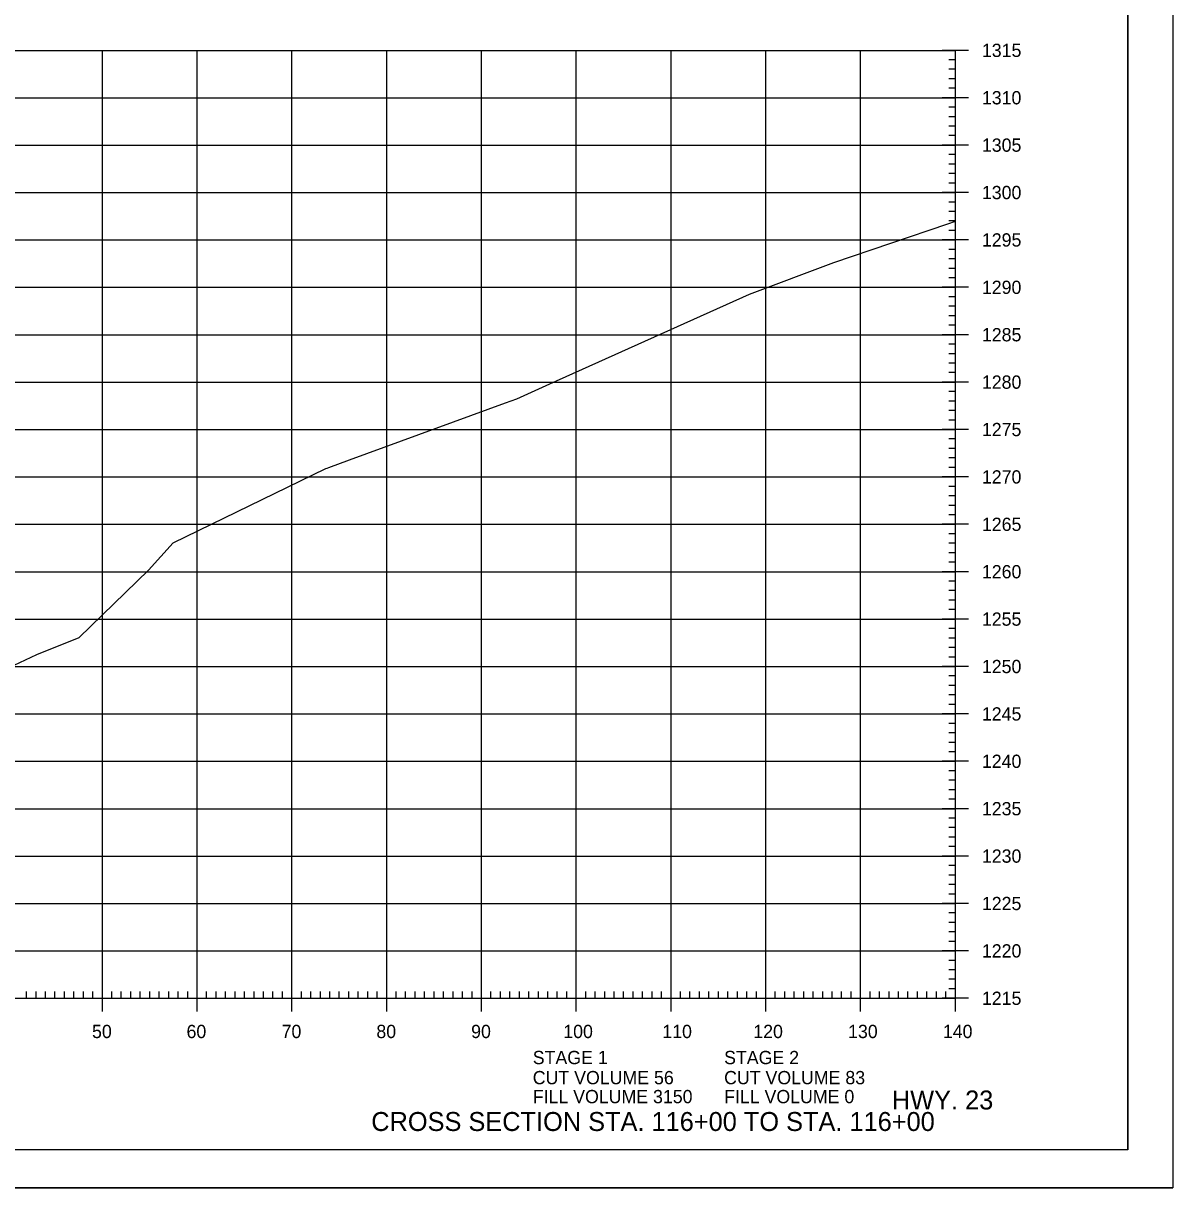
# Model space of a CAD drawing. Extents: x 1406028 to 1412453, y 321733 to 325986.
# Drawn here: x 1406631.5 to 1406752.8, y 324279.4 to 324402.2 of the extents above; entities that cross this region are included whole.
import ezdxf

# ---------------------------------------------------------------- set-up
doc = ezdxf.new("R2010")
doc.units = 0
for name, color, linetype in [('R_Axis', 7, 'Continuous'), ('R_Axis Annot', 7, 'Continuous'), ('R_Border', 7, 'Continuous'), ('R_Draft', 7, 'Continuous'), ('R_Exist Surface', 7, 'Continuous'), ('R_Grid', 7, 'Continuous'), ('R_No Plot', 7, 'Continuous')]:
    doc.layers.add(name, color=color, linetype=linetype)

msp = doc.modelspace()

# ---------------------------------------------------------------- linework, layer by layer
at = {"layer": 'R_Axis'}
for p, q in [((1406731.29, 324399.37), (1406728.49, 324399.37)), ((1406729.89, 324398.37), (1406729.19, 324398.37)), ((1406729.89, 324299.37), (1406729.89, 324399.37)), ((1406729.89, 324397.37), (1406729.19, 324397.37)), ((1406729.89, 324396.37), (1406729.19, 324396.37)), ((1406729.89, 324395.37), (1406729.19, 324395.37)), ((1406731.29, 324394.37), (1406728.49, 324394.37)), ((1406729.89, 324393.37), (1406729.19, 324393.37)), ((1406729.89, 324392.37), (1406729.19, 324392.37)), ((1406729.89, 324391.37), (1406729.19, 324391.37)), ((1406729.89, 324390.37), (1406729.19, 324390.37)), ((1406731.29, 324389.37), (1406728.49, 324389.37)), ((1406729.89, 324388.37), (1406729.19, 324388.37)), ((1406729.89, 324387.37), (1406729.19, 324387.37)), ((1406729.89, 324386.37), (1406729.19, 324386.37)), ((1406729.89, 324385.37), (1406729.19, 324385.37)), ((1406731.29, 324384.37), (1406728.49, 324384.37)), ((1406729.89, 324383.37), (1406729.19, 324383.37)), ((1406729.89, 324382.37), (1406729.19, 324382.37)), ((1406729.89, 324381.37), (1406729.19, 324381.37)), ((1406729.89, 324380.37), (1406729.19, 324380.37)), ((1406731.29, 324379.37), (1406728.49, 324379.37)), ((1406729.89, 324378.37), (1406729.19, 324378.37)), ((1406729.89, 324377.37), (1406729.19, 324377.37)), ((1406729.89, 324376.37), (1406729.19, 324376.37)), ((1406729.89, 324375.37), (1406729.19, 324375.37)), ((1406731.29, 324374.37), (1406728.49, 324374.37)), ((1406729.89, 324373.37), (1406729.19, 324373.37)), ((1406729.89, 324372.37), (1406729.19, 324372.37)), ((1406729.89, 324371.37), (1406729.19, 324371.37)), ((1406729.89, 324370.37), (1406729.19, 324370.37)), ((1406731.29, 324369.37), (1406728.49, 324369.37)), ((1406729.89, 324368.37), (1406729.19, 324368.37)), ((1406729.89, 324367.37), (1406729.19, 324367.37)), ((1406729.89, 324366.37), (1406729.19, 324366.37)), ((1406729.89, 324365.37), (1406729.19, 324365.37)), ((1406731.29, 324364.37), (1406728.49, 324364.37)), ((1406729.89, 324363.37), (1406729.19, 324363.37)), ((1406729.89, 324362.37), (1406729.19, 324362.37)), ((1406729.89, 324361.37), (1406729.19, 324361.37)), ((1406729.89, 324360.37), (1406729.19, 324360.37)), ((1406731.29, 324359.37), (1406728.49, 324359.37)), ((1406729.89, 324358.37), (1406729.19, 324358.37)), ((1406729.89, 324357.37), (1406729.19, 324357.37)), ((1406729.89, 324356.37), (1406729.19, 324356.37)), ((1406729.89, 324355.37), (1406729.19, 324355.37)), ((1406731.29, 324354.37), (1406728.49, 324354.37)), ((1406729.89, 324353.37), (1406729.19, 324353.37)), ((1406729.89, 324352.37), (1406729.19, 324352.37)), ((1406729.89, 324351.37), (1406729.19, 324351.37)), ((1406729.89, 324350.37), (1406729.19, 324350.37)), ((1406731.29, 324349.37), (1406728.49, 324349.37)), ((1406729.89, 324348.37), (1406729.19, 324348.37)), ((1406729.89, 324347.37), (1406729.19, 324347.37)), ((1406729.89, 324346.37), (1406729.19, 324346.37)), ((1406731.29, 324344.37), (1406728.49, 324344.37)), ((1406729.89, 324345.37), (1406729.19, 324345.37)), ((1406729.89, 324343.37), (1406729.19, 324343.37)), ((1406729.89, 324342.37), (1406729.19, 324342.37)), ((1406729.89, 324341.37), (1406729.19, 324341.37)), ((1406731.29, 324339.37), (1406728.49, 324339.37)), ((1406729.89, 324340.37), (1406729.19, 324340.37)), ((1406729.89, 324338.37), (1406729.19, 324338.37)), ((1406729.89, 324337.37), (1406729.19, 324337.37)), ((1406729.89, 324336.37), (1406729.19, 324336.37)), ((1406729.89, 324335.37), (1406729.19, 324335.37)), ((1406731.29, 324334.37), (1406728.49, 324334.37)), ((1406729.89, 324333.37), (1406729.19, 324333.37)), ((1406729.89, 324332.37), (1406729.19, 324332.37)), ((1406729.89, 324331.37), (1406729.19, 324331.37)), ((1406729.89, 324330.37), (1406729.19, 324330.37)), ((1406731.29, 324329.37), (1406728.49, 324329.37)), ((1406729.89, 324328.37), (1406729.19, 324328.37)), ((1406729.89, 324327.37), (1406729.19, 324327.37)), ((1406729.89, 324326.37), (1406729.19, 324326.37)), ((1406729.89, 324325.37), (1406729.19, 324325.37)), ((1406731.29, 324324.37), (1406728.49, 324324.37)), ((1406729.89, 324323.37), (1406729.19, 324323.37)), ((1406729.89, 324322.37), (1406729.19, 324322.37)), ((1406729.89, 324321.37), (1406729.19, 324321.37)), ((1406729.89, 324320.37), (1406729.19, 324320.37)), ((1406731.29, 324319.37), (1406728.49, 324319.37)), ((1406729.89, 324318.37), (1406729.19, 324318.37)), ((1406729.89, 324317.37), (1406729.19, 324317.37)), ((1406729.89, 324316.37), (1406729.19, 324316.37)), ((1406729.89, 324315.37), (1406729.19, 324315.37)), ((1406731.29, 324314.37), (1406728.49, 324314.37)), ((1406729.89, 324313.37), (1406729.19, 324313.37)), ((1406729.89, 324312.37), (1406729.19, 324312.37)), ((1406729.89, 324311.37), (1406729.19, 324311.37)), ((1406729.89, 324310.37), (1406729.19, 324310.37)), ((1406731.29, 324309.37), (1406728.49, 324309.37)), ((1406729.89, 324308.37), (1406729.19, 324308.37)), ((1406729.89, 324307.37), (1406729.19, 324307.37)), ((1406729.89, 324306.37), (1406729.19, 324306.37)), ((1406729.89, 324305.37), (1406729.19, 324305.37)), ((1406731.29, 324304.37), (1406728.49, 324304.37)), ((1406729.89, 324303.37), (1406729.19, 324303.37)), ((1406729.89, 324302.37), (1406729.19, 324302.37)), ((1406729.89, 324301.37), (1406729.19, 324301.37)), ((1406631.89, 324299.37), (1406631.89, 324300.07)), ((1406632.89, 324299.37), (1406632.89, 324300.07)), ((1406633.89, 324299.37), (1406633.89, 324300.07)), ((1406634.89, 324299.37), (1406634.89, 324300.07)), ((1406635.89, 324299.37), (1406635.89, 324300.07)), ((1406636.89, 324299.37), (1406636.89, 324300.07)), ((1406637.89, 324299.37), (1406637.89, 324300.07)), ((1406638.89, 324299.37), (1406638.89, 324300.07)), ((1406639.89, 324297.97), (1406639.89, 324300.77)), ((1406640.89, 324299.37), (1406640.89, 324300.07)), ((1406641.89, 324299.37), (1406641.89, 324300.07)), ((1406642.89, 324299.37), (1406642.89, 324300.07)), ((1406643.89, 324299.37), (1406643.89, 324300.07)), ((1406644.89, 324299.37), (1406644.89, 324300.07)), ((1406645.89, 324299.37), (1406645.89, 324300.07)), ((1406646.89, 324299.37), (1406646.89, 324300.07)), ((1406647.89, 324299.37), (1406647.89, 324300.07)), ((1406648.89, 324299.37), (1406648.89, 324300.07)), ((1406649.89, 324297.97), (1406649.89, 324300.77)), ((1406650.89, 324299.37), (1406650.89, 324300.07)), ((1406651.89, 324299.37), (1406651.89, 324300.07)), ((1406652.89, 324299.37), (1406652.89, 324300.07)), ((1406653.89, 324299.37), (1406653.89, 324300.07)), ((1406654.89, 324299.37), (1406654.89, 324300.07)), ((1406655.89, 324299.37), (1406655.89, 324300.07)), ((1406656.89, 324299.37), (1406656.89, 324300.07)), ((1406657.89, 324299.37), (1406657.89, 324300.07)), ((1406658.89, 324299.37), (1406658.89, 324300.07)), ((1406659.89, 324297.97), (1406659.89, 324300.77)), ((1406660.89, 324299.37), (1406660.89, 324300.07)), ((1406661.89, 324299.37), (1406661.89, 324300.07)), ((1406662.89, 324299.37), (1406662.89, 324300.07)), ((1406663.89, 324299.37), (1406663.89, 324300.07)), ((1406664.89, 324299.37), (1406664.89, 324300.07)), ((1406665.89, 324299.37), (1406665.89, 324300.07)), ((1406666.89, 324299.37), (1406666.89, 324300.07)), ((1406667.89, 324299.37), (1406667.89, 324300.07)), ((1406668.89, 324299.37), (1406668.89, 324300.07)), ((1406669.89, 324297.97), (1406669.89, 324300.77)), ((1406670.89, 324299.37), (1406670.89, 324300.07)), ((1406671.89, 324299.37), (1406671.89, 324300.07)), ((1406672.89, 324299.37), (1406672.89, 324300.07)), ((1406673.89, 324299.37), (1406673.89, 324300.07)), ((1406674.89, 324299.37), (1406674.89, 324300.07)), ((1406675.89, 324299.37), (1406675.89, 324300.07)), ((1406676.89, 324299.37), (1406676.89, 324300.07)), ((1406677.89, 324299.37), (1406677.89, 324300.07)), ((1406678.89, 324299.37), (1406678.89, 324300.07)), ((1406679.89, 324297.97), (1406679.89, 324300.77)), ((1406680.89, 324299.37), (1406680.89, 324300.07)), ((1406681.89, 324299.37), (1406681.89, 324300.07)), ((1406682.89, 324299.37), (1406682.89, 324300.07)), ((1406683.89, 324299.37), (1406683.89, 324300.07)), ((1406684.89, 324299.37), (1406684.89, 324300.07)), ((1406685.89, 324299.37), (1406685.89, 324300.07)), ((1406686.89, 324299.37), (1406686.89, 324300.07)), ((1406687.89, 324299.37), (1406687.89, 324300.07)), ((1406688.89, 324299.37), (1406688.89, 324300.07)), ((1406689.89, 324297.97), (1406689.89, 324300.77)), ((1406690.89, 324299.37), (1406690.89, 324300.07)), ((1406691.89, 324299.37), (1406691.89, 324300.07)), ((1406692.89, 324299.37), (1406692.89, 324300.07)), ((1406693.89, 324299.37), (1406693.89, 324300.07)), ((1406694.89, 324299.37), (1406694.89, 324300.07)), ((1406695.89, 324299.37), (1406695.89, 324300.07)), ((1406696.89, 324299.37), (1406696.89, 324300.07)), ((1406697.89, 324299.37), (1406697.89, 324300.07)), ((1406698.89, 324299.37), (1406698.89, 324300.07)), ((1406699.89, 324297.97), (1406699.89, 324300.77)), ((1406700.89, 324299.37), (1406700.89, 324300.07)), ((1406701.89, 324299.37), (1406701.89, 324300.07)), ((1406702.89, 324299.37), (1406702.89, 324300.07)), ((1406703.89, 324299.37), (1406703.89, 324300.07)), ((1406704.89, 324299.37), (1406704.89, 324300.07)), ((1406705.89, 324299.37), (1406705.89, 324300.07)), ((1406706.89, 324299.37), (1406706.89, 324300.07)), ((1406707.89, 324299.37), (1406707.89, 324300.07)), ((1406708.89, 324299.37), (1406708.89, 324300.07)), ((1406709.89, 324297.97), (1406709.89, 324300.77)), ((1406710.89, 324299.37), (1406710.89, 324300.07)), ((1406711.89, 324299.37), (1406711.89, 324300.07)), ((1406712.89, 324299.37), (1406712.89, 324300.07)), ((1406713.89, 324299.37), (1406713.89, 324300.07)), ((1406714.89, 324299.37), (1406714.89, 324300.07)), ((1406715.89, 324299.37), (1406715.89, 324300.07)), ((1406716.89, 324299.37), (1406716.89, 324300.07)), ((1406717.89, 324299.37), (1406717.89, 324300.07)), ((1406718.89, 324299.37), (1406718.89, 324300.07)), ((1406719.89, 324297.97), (1406719.89, 324300.77)), ((1406720.89, 324299.37), (1406720.89, 324300.07)), ((1406721.89, 324299.37), (1406721.89, 324300.07)), ((1406722.89, 324299.37), (1406722.89, 324300.07)), ((1406723.89, 324299.37), (1406723.89, 324300.07)), ((1406724.89, 324299.37), (1406724.89, 324300.07)), ((1406725.89, 324299.37), (1406725.89, 324300.07)), ((1406726.89, 324299.37), (1406726.89, 324300.07)), ((1406727.89, 324299.37), (1406727.89, 324300.07)), ((1406728.89, 324299.37), (1406728.89, 324300.07)), ((1406729.89, 324300.37), (1406729.19, 324300.37)), ((1406729.89, 324297.97), (1406729.89, 324300.77)), ((1406449.89, 324299.37), (1406729.89, 324299.37)), ((1406731.29, 324299.37), (1406728.49, 324299.37))]:
    msp.add_line(p, q, dxfattribs=at)
at = {"layer": 'R_Border'}
for q in [(1406748.07, 324488.83), (1406431.89, 324283.37)]:
    msp.add_line((1406748.07, 324283.37), q, dxfattribs=at)
at = {"layer": 'R_Exist Surface'}
msp.add_lwpolyline([(1406630.6, 324334.5), (1406632.99, 324335.62), (1406637.44, 324337.42), (1406644.74, 324344.52), (1406647.35, 324347.43), (1406663.46, 324355.24), (1406663.61, 324355.31), (1406663.77, 324355.37), (1406665.95, 324356.16), (1406682.42, 324362.17), (1406683.62, 324362.59), (1406687.11, 324364.2), (1406708.17, 324373.65), (1406717.06, 324376.98), (1406729.09, 324381.06), (1406729.89, 324381.34)], dxfattribs=at)
at = {"layer": 'R_Grid'}
for p, q in [((1406449.89, 324399.37), (1406729.89, 324399.37)), ((1406639.89, 324299.37), (1406639.89, 324399.37)), ((1406649.89, 324299.37), (1406649.89, 324399.37)), ((1406659.89, 324299.37), (1406659.89, 324399.37)), ((1406669.89, 324299.37), (1406669.89, 324399.37)), ((1406679.89, 324299.37), (1406679.89, 324399.37)), ((1406689.89, 324299.37), (1406689.89, 324399.37)), ((1406699.89, 324299.37), (1406699.89, 324399.37)), ((1406709.89, 324299.37), (1406709.89, 324399.37)), ((1406719.89, 324299.37), (1406719.89, 324399.37)), ((1406729.89, 324299.37), (1406729.89, 324399.37)), ((1406449.89, 324394.37), (1406729.89, 324394.37)), ((1406449.89, 324389.37), (1406729.89, 324389.37)), ((1406449.89, 324384.37), (1406729.89, 324384.37)), ((1406449.89, 324379.37), (1406729.89, 324379.37)), ((1406449.89, 324374.37), (1406729.89, 324374.37)), ((1406449.89, 324369.37), (1406729.89, 324369.37)), ((1406449.89, 324364.37), (1406729.89, 324364.37)), ((1406449.89, 324359.37), (1406729.89, 324359.37)), ((1406449.89, 324354.37), (1406729.89, 324354.37)), ((1406449.89, 324349.37), (1406729.89, 324349.37)), ((1406449.89, 324344.37), (1406729.89, 324344.37)), ((1406449.89, 324339.37), (1406729.89, 324339.37)), ((1406449.89, 324334.37), (1406729.89, 324334.37)), ((1406449.89, 324329.37), (1406729.89, 324329.37)), ((1406449.89, 324324.37), (1406729.89, 324324.37)), ((1406449.89, 324319.37), (1406729.89, 324319.37)), ((1406449.89, 324314.37), (1406729.89, 324314.37)), ((1406449.89, 324309.37), (1406729.89, 324309.37)), ((1406449.89, 324304.37), (1406729.89, 324304.37)), ((1406449.89, 324299.37), (1406729.89, 324299.37))]:
    msp.add_line(p, q, dxfattribs=at)
at = {"layer": 'R_No Plot'}
msp.add_line((1406419.49, 324279.39), (1406752.82, 324279.39), dxfattribs=at)
for points in [[(1406419.48, 324492.72), (1406752.82, 324492.72), (1406752.82, 324279.39), (1406419.48, 324279.39)], [(1406665.81, 324488.83), (1406685.43, 324488.83), (1406685.43, 324478.95), (1406701.54, 324478.95), (1406724.74, 324478.95), (1406724.74, 324454.62), (1406748.07, 324454.62), (1406748.07, 324283.37), (1406431.89, 324283.37), (1406431.89, 324488.83)]]:
    msp.add_lwpolyline(points, close=True, dxfattribs=at)

# ---------------------------------------------------------------- texts
at = {"layer": 'R_Axis Annot'}
for s, p in [('1315', (1406732.69, 324398.67)), ('1310', (1406732.69, 324393.67)), ('1305', (1406732.69, 324388.67)), ('1300', (1406732.69, 324383.67)), ('1295', (1406732.69, 324378.67)), ('1290', (1406732.69, 324373.67)), ('1285', (1406732.69, 324368.67)), ('1280', (1406732.69, 324363.67)), ('1275', (1406732.69, 324358.67)), ('1270', (1406732.69, 324353.67)), ('1265', (1406732.69, 324348.67)), ('1260', (1406732.69, 324343.67)), ('1255', (1406732.69, 324338.67)), ('1250', (1406732.69, 324333.67)), ('1245', (1406732.69, 324328.67)), ('1240', (1406732.69, 324323.67)), ('1235', (1406732.69, 324318.67)), ('1230', (1406732.69, 324313.67)), ('1225', (1406732.69, 324308.67)), ('1220', (1406732.69, 324303.67)), ('1215', (1406732.69, 324298.67)), ('50', (1406638.8, 324295.17)), ('60', (1406648.77, 324295.17)), ('70', (1406658.8, 324295.17)), ('80', (1406668.8, 324295.17)), ('90', (1406678.8, 324295.17)), ('100', (1406688.52, 324295.17)), ('110', (1406698.97, 324295.17)), ('120', (1406708.57, 324295.17)), ('130', (1406718.57, 324295.17)), ('140', (1406728.57, 324295.17)), ('STAGE 1', (1406685.3, 324292.42)), ('STAGE 2', (1406705.49, 324292.42)), ('CUT VOLUME 56', (1406685.3, 324290.3)), ('CUT VOLUME 83', (1406705.49, 324290.3)), ('FILL VOLUME 3150', (1406685.3, 324288.3)), ('FILL VOLUME 0', (1406705.49, 324288.3))]:
    msp.add_text(s, height=1.4, dxfattribs=at).set_placement(p)
at = {"layer": 'R_Draft'}
for s, p in [('HWY. 23', (1406723.19, 324287.64)), ('CROSS SECTION STA. 116+00 TO STA. 116+00', (1406668.26, 324285.37))]:
    msp.add_text(s, height=2, dxfattribs=at).set_placement(p)
at = {"layer": 'R_No Plot'}
for p in [(1406729.04, 324381.01), (1406708.13, 324373.6), (1406683.58, 324362.54), (1406663.57, 324355.26), (1406647.3, 324347.38), (1406637.4, 324337.37)]:
    msp.add_text('+', height=0.1, dxfattribs=at).set_placement(p)

doc.saveas('drawing.dxf')
